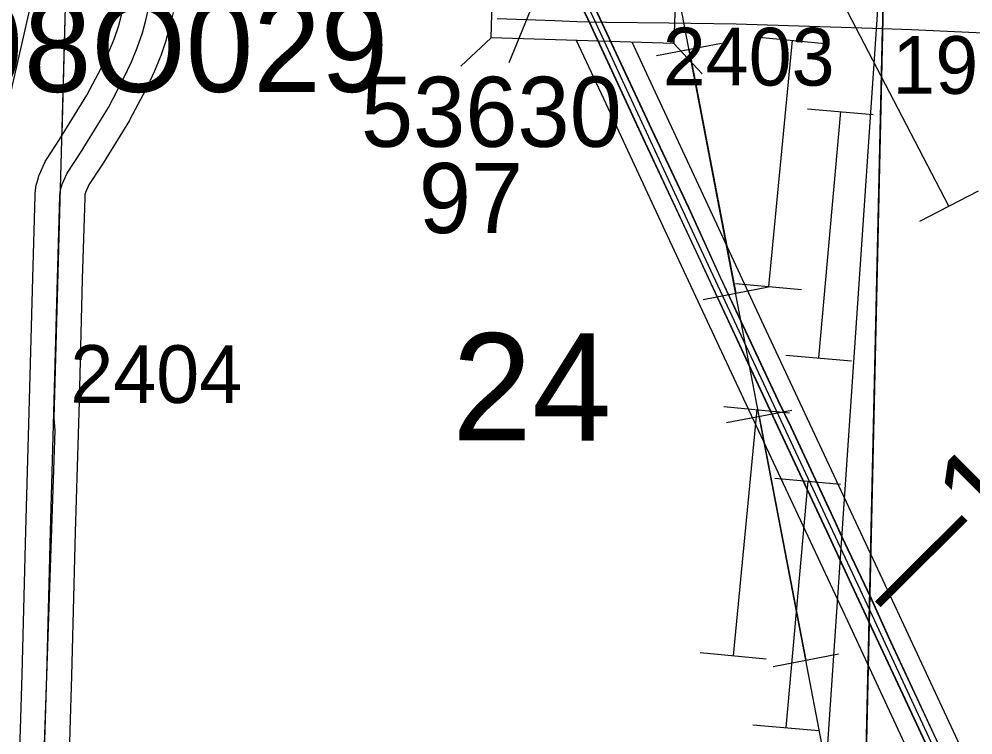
# Model space of a CAD drawing. Extents: x -157.2 to -99.3, y 12.2 to 46.2.
# Drawn here: x -142.044 to -140.888, y 19.169 to 20.037 of the extents above; entities that cross this region are included whole.
import ezdxf

# ---------------------------------------------------------------- set-up
doc = ezdxf.new("R2010")
doc.units = 0
for name, color, linetype in [('tdCoDivCarto', 7, 'Continuous'), ('tdCoHydroRiver', 7, 'Continuous'), ('tdCoInt', 7, 'Continuous'), ('tdCoIntCL', 7, 'Continuous'), ('tdCoIntRte', 7, 'Continuous'), ('tdCoPipe', 7, 'Continuous'), ('tdCoPipe1', 7, 'Continuous'), ('tdCoPipe2', 7, 'Continuous'), ('tdCoSecRdNmbr', 7, 'Continuous'), ('tdCoSecRteBand', 7, 'Continuous'), ('tdCoSecRteCL', 7, 'Continuous'), ('tdCoSectLine', 7, 'Continuous'), ('tdCoSectLinePart', 7, 'Continuous'), ('tdCoSectNmbr', 7, 'Continuous'), ('tdCoStrucNonDivPri', 7, 'Continuous'), ('tdCoStrucPriMaintName', 7, 'Continuous'), ('tdCoStrucSecCoName', 7, 'Continuous'), ('tdCoStrucSecFHWANum', 7, 'Continuous'), ('tdCoSurfGravel', 7, 'Continuous'), ('tdCoTwpBndry', 7, 'Continuous'), ('tdCoTwpBndryShd', 7, 'Continuous'), ('tdStHwyIntRefPost1', 7, 'Continuous')]:
    doc.layers.add(name, color=color, linetype=linetype)

msp = doc.modelspace()

# ---------------------------------------------------------------- linework, layer by layer
at = {"layer": 'tdCoDivCarto'}
for points in [[(-141.7665, 20.9185), (-141.7066, 20.7905), (-141.6455, 20.6591), (-141.586, 20.5328), (-141.5288, 20.4098), (-141.4714, 20.2857), (-141.4127, 20.1602), (-141.3675, 20.0639), (-141.351, 20.0288), (-141.2884, 19.8934), (-141.2265, 19.7609), (-141.1636, 19.6258), (-141.1012, 19.4921), (-141.0627, 19.4098), (-141.0383, 19.3575), (-140.9735, 19.2182), (-140.9212, 19.1062)], [(-141.7665, 20.9185), (-141.7066, 20.7905), (-141.6455, 20.6591), (-141.586, 20.5328), (-141.5288, 20.4098), (-141.4714, 20.2857), (-141.4127, 20.1602), (-141.3675, 20.0639), (-141.351, 20.0288), (-141.2884, 19.8934), (-141.2265, 19.7609), (-141.1636, 19.6258), (-141.1012, 19.4921), (-141.0627, 19.4098), (-141.0383, 19.3575), (-140.9735, 19.2182), (-140.9212, 19.1062)], [(-140.9296, 19.1568), (-140.9902, 19.2873), (-141.0119, 19.3349), (-141.0469, 19.4089), (-141.0548, 19.4259), (-141.1084, 19.5415), (-141.1239, 19.5741), (-141.172, 19.6767), (-141.1942, 19.7238), (-141.2324, 19.8076), (-141.2775, 19.9036), (-141.3372, 20.0316), (-141.352, 20.0634), (-141.3535, 20.0665)], [(-140.9296, 19.1568), (-140.9902, 19.2873), (-141.0119, 19.3349), (-141.0469, 19.4089), (-141.0548, 19.4259), (-141.1084, 19.5415), (-141.1239, 19.5741), (-141.172, 19.6767), (-141.1942, 19.7238), (-141.2324, 19.8076), (-141.2775, 19.9036), (-141.3372, 20.0316), (-141.352, 20.0634), (-141.3535, 20.0665)]]:
    msp.add_lwpolyline(points, dxfattribs=at)
at = {"layer": 'tdCoHydroRiver'}
msp.add_lwpolyline([(-141.8975, 21.0129), (-141.8354, 20.886), (-141.8358, 20.8734), (-141.7928, 20.7883), (-141.7901, 20.7266), (-142.0016, 20.1508), (-142.0165, 20.1292), (-142.0225, 20.0899), (-142.0686, 19.8893), (-142.1688, 19.6747), (-142.2153, 19.5562)], dxfattribs=at)
at = {"layer": 'tdCoInt'}
for points in [[(-140.9554, 19.124), (-141.0374, 19.3005), (-141.199, 19.6459), (-141.2586, 19.7742), (-141.3357, 19.9402), (-141.3687, 20.011)], [(-140.9011, 19.1493), (-140.9831, 19.3258), (-141.1447, 19.6713), (-141.2042, 19.7995), (-141.2813, 19.9655), (-141.3015, 20.0089)]]:
    msp.add_lwpolyline(points, dxfattribs=at)
at = {"layer": 'tdCoIntCL'}
msp.add_lwpolyline([(-140.9283, 19.1366), (-141.0102, 19.3131), (-141.1718, 19.6586), (-141.2314, 19.7868), (-141.3154, 19.9679), (-141.3452, 20.0317), (-141.3601, 20.0636), (-141.378, 20.1019), (-141.4049, 20.1587), (-141.4095, 20.1685), (-141.4095, 20.1685), (-141.4645, 20.2865), (-141.5229, 20.412), (-141.6177, 20.6148), (-141.6412, 20.665), (-141.698, 20.7878), (-141.7062, 20.8054), (-141.7699, 20.9404)], dxfattribs=at)
at = {"layer": 'tdCoIntRte'}
for points in [[(-141.7669, 20.9185), (-141.707, 20.7905), (-141.6458, 20.6591), (-141.5864, 20.5328), (-141.5292, 20.4098), (-141.4717, 20.2857), (-141.413, 20.1602), (-141.3679, 20.0639), (-141.3514, 20.0288), (-141.2888, 19.8934), (-141.2269, 19.7609), (-141.164, 19.6258), (-141.1016, 19.4921), (-141.0631, 19.4098), (-141.0387, 19.3575), (-140.9738, 19.2182), (-140.9216, 19.1062)], [(-141.7669, 20.9185), (-141.707, 20.7905), (-141.6458, 20.6591), (-141.5864, 20.5328), (-141.5292, 20.4098), (-141.4717, 20.2857), (-141.413, 20.1602), (-141.3679, 20.0639), (-141.3514, 20.0288), (-141.2888, 19.8934), (-141.2269, 19.7609), (-141.164, 19.6258), (-141.1016, 19.4921), (-141.0631, 19.4098), (-141.0387, 19.3575), (-140.9738, 19.2182), (-140.9216, 19.1062)], [(-140.9299, 19.1568), (-140.9906, 19.2873), (-141.0123, 19.3349), (-141.0473, 19.4089), (-141.0552, 19.4259), (-141.1087, 19.5415), (-141.1243, 19.5741), (-141.1724, 19.6767), (-141.1945, 19.7238), (-141.2328, 19.8076), (-141.2779, 19.9036), (-141.3376, 20.0316), (-141.3524, 20.0634)], [(-140.9299, 19.1568), (-140.9906, 19.2873), (-141.0123, 19.3349), (-141.0473, 19.4089), (-141.0552, 19.4259), (-141.1087, 19.5415), (-141.1243, 19.5741), (-141.1724, 19.6767), (-141.1945, 19.7238), (-141.2328, 19.8076), (-141.2779, 19.9036), (-141.3376, 20.0316), (-141.3524, 20.0634)]]:
    msp.add_lwpolyline(points, dxfattribs=at)
at = {"layer": 'tdCoPipe'}
for p, q in [((-141.272, 19.9927), (-141.193, 20.0078)), ((-140.8822, 19.8285), (-140.9533, 19.7916)), ((-141.2155, 19.697), (-141.1364, 19.7121)), ((-141.187, 19.5476), (-141.108, 19.5627)), ((-141.1305, 19.2519), (-141.0513, 19.267))]:
    msp.add_line(p, q, dxfattribs=at)
for points in [[(-140.7939, 17.0158), (-140.771, 17.5856), (-141.3809, 20.7773), (-141.4061, 21.2289), (-141.2323, 21.3329), (-141.6198, 22.0977), (-141.6066, 22.6198), (-141.8066, 22.8738), (-141.7898, 23.3819), (-141.8432, 23.4016), (-141.8037, 25.2014)], [(-141.2153, 16.938), (-140.9814, 20.3752), (-141.4436, 21.0626), (-141.5868, 21.3985), (-141.9847, 21.8504), (-142.4211, 22.4672), (-142.8261, 23.0072), (-142.8339, 23.1351), (-143.0775, 23.1591), (-143.0801, 23.5043)], [(-140.9177, 19.81), (-141.0559, 20.0763)], [(-141.2325, 20.0003), (-141.176, 19.7045)], [(-141.1474, 19.5552), (-141.0909, 19.2595)]]:
    msp.add_lwpolyline(points, dxfattribs=at)
at = {"layer": 'tdCoPipe1'}
for p, q in [((-141.089, 19.9283), (-141.0092, 19.9213)), ((-141.1154, 19.6295), (-141.0356, 19.6224)), ((-141.1287, 19.4801), (-141.0488, 19.473)), ((-141.1551, 19.1812), (-141.0752, 19.1742))]:
    msp.add_line(p, q, dxfattribs=at)
for points in [[(-141.0491, 19.9248), (-141.0755, 19.626)], [(-141.0887, 19.4765), (-141.1151, 19.1777)]]:
    msp.add_lwpolyline(points, dxfattribs=at)
at = {"layer": 'tdCoPipe2'}
for p, q in [((-141.1476, 20.0152), (-141.0678, 20.0075)), ((-141.1761, 19.7165), (-141.0963, 19.7089)), ((-141.1904, 19.5672), (-141.1106, 19.5596)), ((-141.2189, 19.2686), (-141.1391, 19.2609))]:
    msp.add_line(p, q, dxfattribs=at)
for points in [[(-141.1077, 20.0113), (-141.1362, 19.7127)], [(-141.1505, 19.5634), (-141.179, 19.2647)]]:
    msp.add_lwpolyline(points, dxfattribs=at)
at = {"layer": 'tdCoSecRteBand'}
for points in [[(-141.8579, 20.045), (-141.8616, 20.029), (-141.8617, 20.0286), (-141.8619, 20.0281), (-141.8661, 20.0126), (-141.8663, 20.0117), (-141.8666, 20.0108), (-141.8728, 19.9925), (-141.8731, 19.9917), (-141.8734, 19.9908), (-141.8803, 19.9738), (-141.8806, 19.973), (-141.881, 19.9722), (-141.8906, 19.952), (-141.8909, 19.9514), (-141.8912, 19.9509), (-141.9097, 19.9159), (-141.9102, 19.915), (-141.9107, 19.9141), (-141.9447, 19.8591), (-141.9449, 19.8588), (-141.9451, 19.8585), (-141.9598, 19.8359), (-141.9639, 19.8265), (-141.9646, 19.8241), (-141.9649, 19.8204), (-141.9679, 19.7216), (-141.9718, 19.5732), (-141.9718, 19.5732), (-141.9718, 19.5732), (-141.9763, 19.4146), (-141.9809, 19.2405), (-141.9809, 19.2405), (-141.9809, 19.2405), (-141.9829, 19.1741), (-141.9843, 19.1269)], [(-142.0442, 19.1286), (-142.0429, 19.1759), (-142.0429, 19.1759), (-142.0429, 19.1759), (-142.0409, 19.2422), (-142.0362, 19.4163), (-142.0362, 19.4163), (-142.0362, 19.4163), (-142.0318, 19.5748), (-142.0279, 19.7233), (-142.0279, 19.7233), (-142.0278, 19.7234), (-142.0249, 19.8232), (-142.0249, 19.8243), (-142.0248, 19.8253), (-142.024, 19.8327), (-142.0237, 19.8354), (-142.023, 19.838), (-142.021, 19.8449), (-142.0205, 19.8468), (-142.0197, 19.8487), (-142.0138, 19.8622), (-142.0128, 19.8645), (-142.0114, 19.8666), (-141.9956, 19.891), (-141.9623, 19.9448), (-141.9445, 19.9783), (-141.9356, 19.9972), (-141.9293, 20.0126), (-141.9237, 20.0291), (-141.9199, 20.0433)], [(-140.8323, 20.0181), (-140.9631, 20.0242), (-141.01, 20.0256), (-141.1755, 20.0308), (-141.257, 20.032), (-141.3326, 20.0328), (-141.333, 20.0328), (-141.3333, 20.0328), (-141.353, 20.0334), (-141.3684, 20.0339), (-141.3952, 20.0348), (-141.3952, 20.0348), (-141.3953, 20.0348), (-141.4651, 20.0372)]]:
    msp.add_lwpolyline(points, dxfattribs=at)
at = {"layer": 'tdCoSecRteCL'}
msp.add_lwpolyline([(-142.0151, 19.0978), (-142.0129, 19.175), (-142.0109, 19.2413), (-142.0062, 19.4155), (-142.0018, 19.574), (-141.9979, 19.7225), (-141.9949, 19.8224), (-141.9942, 19.8298), (-141.9922, 19.8367), (-141.9863, 19.8502), (-141.9702, 19.8749), (-141.9362, 19.9299), (-141.9177, 19.9649), (-141.9081, 19.9851), (-141.9012, 20.0021), (-141.895, 20.0204), (-141.8908, 20.0359), (-141.8839, 20.0653), (-141.8817, 20.0796)], dxfattribs=at)
at = {"layer": 'tdCoSectLine'}
for points in [[(-142.0155, 19.0978), (-142.0006, 19.5381), (-142.002, 19.553), (-141.9873, 20.0816)], [(-141.0197, 19.061), (-140.9973, 20.0552)]]:
    msp.add_lwpolyline(points, dxfattribs=at)
at = {"layer": 'tdCoSectLinePart'}
for points in [[(-141.9924, 19.8973), (-141.9881, 20.0518)], [(-141.019, 19.091), (-140.998, 20.0253)]]:
    msp.add_lwpolyline(points, dxfattribs=at)
at = {"layer": 'tdCoStrucNonDivPri'}
for p, q in [((-141.4725, 20.0144), (-141.509, 19.9801)), ((-141.2509, 20.0073), (-141.2167, 19.9708))]:
    msp.add_line(p, q, dxfattribs=at)
msp.add_lwpolyline([(-141.4693, 20.1143), (-141.2477, 20.1072), (-141.2509, 20.0073), (-141.4725, 20.0144)], close=True, dxfattribs=at)
at = {"layer": 'tdCoStrucSecFHWANum'}
msp.add_line((-141.4504, 19.9843), (-141.4177, 20.065), dxfattribs=at)
at = {"layer": 'tdCoSurfGravel'}
msp.add_lwpolyline([(-142.0151, 19.0978), (-142.0129, 19.175), (-142.0109, 19.2413), (-142.0062, 19.4155), (-142.0018, 19.574), (-141.9979, 19.7225), (-141.9949, 19.8224), (-141.9942, 19.8298), (-141.9922, 19.8367), (-141.9863, 19.8502), (-141.9702, 19.8749), (-141.9362, 19.9299), (-141.9177, 19.9649), (-141.9081, 19.9851), (-141.9012, 20.0021), (-141.895, 20.0204), (-141.8908, 20.0359), (-141.8839, 20.0653)], dxfattribs=at)
at = {"layer": 'tdCoTwpBndry'}
for points in [[(-141.0125, 19.3831), (-140.998, 20.0253)], [(-141.019, 19.091), (-141.0156, 19.2445)]]:
    msp.add_lwpolyline(points, dxfattribs=at)
at = {"layer": 'tdCoTwpBndryShd'}
msp.add_lwpolyline([(-140.5574, 35.0411), (-140.6069, 34.0205), (-140.6476, 33.0243), (-140.68, 32.0266), (-140.7194, 31.0261), (-140.7542, 30.0172), (-140.7866, 29.0316), (-140.7992, 28.0152), (-140.8137, 27.0113), (-140.8321, 26.0183), (-140.8465, 25.0216), (-140.872, 24.0239), (-140.8917, 23.0263), (-140.9324, 22.0454), (-140.9642, 21.0502), (-140.9973, 20.0552), (-141.0197, 19.061), (-141.0567, 18.0706), (-141.0904, 17.0763)], dxfattribs=at)

# ---------------------------------------------------------------- texts
at = {"layer": 'tdCoSecRdNmbr'}
for s, rotation, p in [('2403', 359.8922, (-141.2644, 19.9567)), ('1901', 359.8932, (-140.9862, 19.9465)), ('2404', 359.8916, (-141.9824, 19.5716))]:
    msp.add_text(s, height=0.07, rotation=rotation, dxfattribs=at).set_placement(p)
at = {"layer": 'tdCoSectNmbr'}
msp.add_text('24', height=0.13, rotation=359.8919, dxfattribs=at).set_placement((-141.5197, 19.5261))
at = {"layer": 'tdCoStrucPriMaintName'}
msp.add_text('97298O029', height=0.11, dxfattribs=at).set_placement((-142.3659, 19.9487))
at = {"layer": 'tdCoStrucSecCoName'}
msp.add_text('97', height=0.085, dxfattribs=at).set_placement((-141.56, 19.7775))
at = {"layer": 'tdCoStrucSecFHWANum'}
msp.add_text('53630', height=0.085, dxfattribs=at).set_placement((-141.6301, 19.8821))
at = {"layer": 'tdStHwyIntRefPost1'}
msp.add_text('‒‒129', height=0.1, rotation=45, dxfattribs=at).set_placement((-140.9776, 19.301))

doc.saveas('drawing.dxf')
